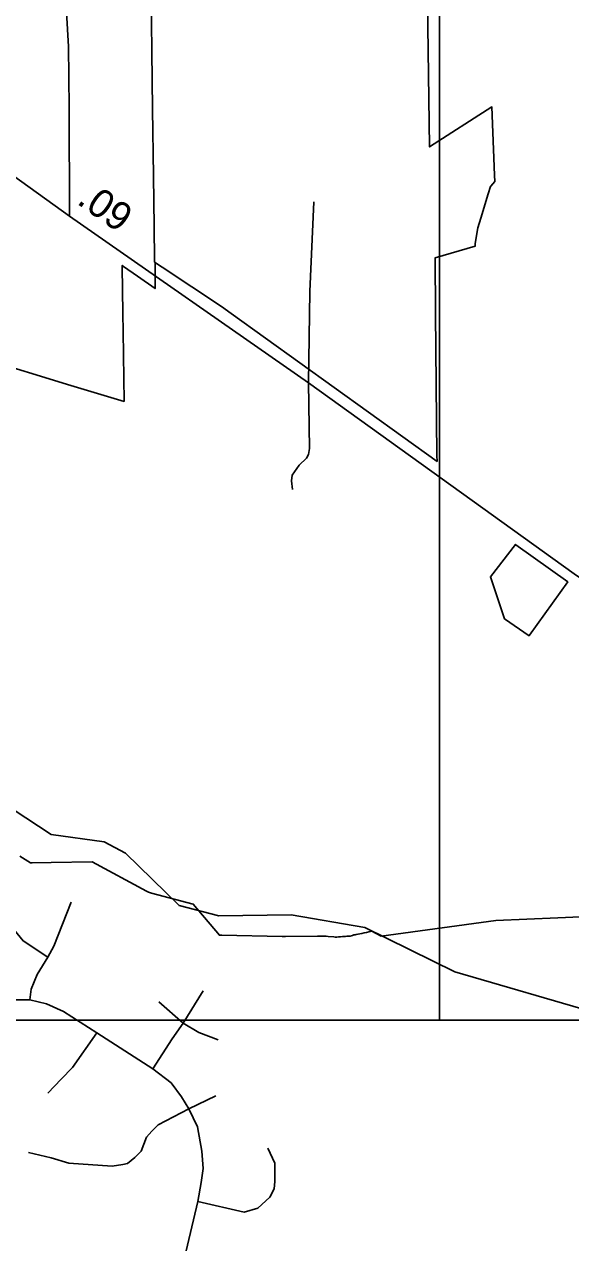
# Model space of a CAD drawing. Extents: x 2220236 to 2384410, y 720751 to 894131.
# Drawn here: x 2344280 to 2346680, y 815997 to 821350 of the extents above; entities that cross this region are included whole.
import ezdxf

# ---------------------------------------------------------------- set-up
doc = ezdxf.new("R2010")
doc.units = 0
doc.layers.add('Default', color=7, linetype='Continuous')

msp = doc.modelspace()

# ---------------------------------------------------------------- linework, layer by layer
at = {"layer": 'Default'}
for p, q in [((2344478.4, 820507.4), (2343633.8, 821113.6)), ((2344977.3, 816961.5), (2345064.7, 817103.7)), ((2344977.3, 816961.5), (2344871.2, 817055.7)), ((2344598, 816918.7), (2344843.8, 816761.2)), ((2345003, 816584.8), (2345121.2, 816641.3)), ((2345041.6, 816177.1), (2344925.1, 815683.9))]:
    msp.add_line(p, q, dxfattribs=at)
for points in [[(2329807.7, 835464.4), (2346103.7, 835464.4), (2346103.7, 816974.9), (2329807.7, 816974.9), (2329807.7, 835464.4)], [(2346103.7, 826026.5), (2370568.5, 826026.5), (2370568.5, 816974.7), (2346103.7, 816974.7), (2346103.7, 826026.5)], [(2344478.4, 820507.4), (2344476.5, 820982.7), (2344473, 821253.3), (2344445.1, 821731.6)], [(2346048.5, 821658.2), (2346060.2, 820811.6), (2346333.8, 820987.3), (2346345.2, 820687.1), (2346346.2, 820659.9), (2346329.2, 820639.2), (2346327.2, 820637.1), (2346317.5, 820604.6), (2346285, 820498), (2346272.2, 820455.7), (2346261, 820387.2), (2346260.2, 820383.2), (2346260.8, 820375.8), (2346084.8, 820324.8), (2346086.2, 820082.6), (2346086.2, 820079.4), (2346092.5, 819455.8), (2346092.8, 819429.9), (2345188.8, 820079.3), (2345146.5, 820109.7), (2344885, 820283.1), (2344864.2, 820297), (2344854, 820304.2), (2344852.2, 820305.6), (2344852, 820315.1), (2344850, 820460.7), (2344847, 820684.1), (2344843.2, 820976.9), (2344834.8, 821615.2)], [(2346048.5, 821658.2), (2346060.2, 820811.6), (2346333.8, 820987.3), (2346345.2, 820687.1), (2346346.2, 820659.9), (2346329.2, 820639.2), (2346327.2, 820637.1), (2346317.5, 820604.6), (2346285, 820498), (2346272.2, 820455.7), (2346261, 820387.2), (2346260.2, 820383.2), (2346260.8, 820375.8), (2346084.8, 820324.8), (2346086.2, 820082.6), (2346086.2, 820079.4), (2346092.5, 819455.8), (2346092.8, 819429.9), (2345188.8, 820079.3), (2345146.5, 820109.7), (2344885, 820283.1), (2344864.2, 820297), (2344854, 820304.2), (2344852.2, 820305.6), (2344852, 820315.1), (2344850, 820460.7), (2344847, 820684.1), (2344843.2, 820976.9), (2344834.8, 821615.2)], [(2344834.8, 821615.2), (2344843.2, 820976.9), (2344847, 820684.1), (2344850, 820460.7), (2344852, 820315.1), (2344852.2, 820305.6), (2344854, 820304.2), (2344854, 820279.7), (2344854, 820188.9), (2344777.2, 820242.9), (2344715.5, 820286.5), (2344709.5, 820290.6), (2344709.5, 820285.9), (2344712.5, 820079.3), (2344713.8, 820001.1), (2344718, 819692.9), (2344484, 819763.7), (2344091, 819882.6)], [(2344834.8, 821615.2), (2344843.2, 820976.9), (2344847, 820684.1), (2344850, 820460.7), (2344852, 820315.1), (2344852.2, 820305.6), (2344854, 820304.2), (2344854, 820279.7), (2344854, 820188.9), (2344777.2, 820242.9), (2344715.5, 820286.5), (2344709.5, 820290.6), (2344709.5, 820285.9), (2344712.5, 820079.3), (2344713.8, 820001.1), (2344718, 819692.9), (2344484, 819763.7), (2344091, 819882.6)], [(2345550.9, 820570.7), (2345534.6, 820176.2), (2345528.6, 819774.9)], [(2348124.6, 817788.7), (2347936.5, 817963.2), (2347678.1, 818197.7), (2347421.9, 818413.9), (2347207.1, 818583.8), (2346695.1, 818936.2), (2345528.6, 819774.9), (2344478.4, 820507.4)], [(2345458.5, 819305.9), (2345453.4, 819343.6), (2345456.8, 819369.2), (2345487.6, 819413.7), (2345520.1, 819444.5), (2345528.6, 819459.9), (2345532, 819485.6), (2345528.6, 819774.9)], [(2346805.5, 817002.9), (2346170.5, 817187), (2345776.4, 817380.9), (2345451.3, 817436.6), (2345134.3, 817433.5), (2344959.4, 817478.8), (2344723.4, 817708.8), (2344630.5, 817757.6), (2344397.4, 817790.6), (2344011.4, 818044), (2343719.4, 818048.5), (2343089.3, 818449.4), (2342894.3, 818730.3), (2342743.4, 818819.3), (2342400.3, 818966.1), (2342240.4, 819113.8)], [(2344259.8, 817695.5), (2344306, 817665.9), (2344314, 817666.1), (2344396.8, 817667.6), (2344577.2, 817670.8), (2344816.2, 817541.6), (2344825.8, 817536.3), (2344837.8, 817533.1), (2345022, 817484), (2345136.5, 817347.8), (2345147.5, 817347.5), (2345411.8, 817341.8), (2345427, 817342), (2345567, 817344), (2345581.5, 817343.1), (2345590.5, 817343.6), (2345597.2, 817343), (2345605.5, 817342.8), (2345614.8, 817341.9), (2345639.8, 817340.4), (2345645, 817339.8), (2345652.2, 817339.8), (2345660.5, 817340.6), (2345669.5, 817341.1), (2345677.5, 817341.4), (2345685.2, 817342), (2345691, 817342.4), (2345696.8, 817342.8), (2345704, 817343.3), (2345710.8, 817343.6), (2345721.2, 817346.6), (2345727.2, 817348.7), (2345732.8, 817350), (2345738, 817350.9), (2345745, 817351.8), (2345754, 817353.8), (2345761.8, 817355.6), (2345772.5, 817357.8), (2345783, 817359.8), (2345794, 817362.2), (2345800.5, 817363.9), (2345806.2, 817365.6), (2345847.8, 817343.4), (2346351.8, 817412.8), (2346624, 817424.3), (2346920.5, 817436.9)], [(2344259.8, 817695.5), (2344306, 817665.9), (2344314, 817666.1), (2344396.8, 817667.6), (2344577.2, 817670.8), (2344816.2, 817541.6), (2344825.8, 817536.3), (2344837.8, 817533.1), (2345022, 817484), (2345136.5, 817347.8), (2345147.5, 817347.5), (2345411.8, 817341.8), (2345427, 817342), (2345567, 817344), (2345581.5, 817343.1), (2345590.5, 817343.6), (2345597.2, 817343), (2345605.5, 817342.8), (2345614.8, 817341.9), (2345639.8, 817340.4), (2345645, 817339.8), (2345652.2, 817339.8), (2345660.5, 817340.6), (2345669.5, 817341.1), (2345677.5, 817341.4), (2345685.2, 817342), (2345691, 817342.4), (2345696.8, 817342.8), (2345704, 817343.3), (2345710.8, 817343.6), (2345721.2, 817346.6), (2345727.2, 817348.7), (2345732.8, 817350), (2345738, 817350.9), (2345745, 817351.8), (2345754, 817353.8), (2345761.8, 817355.6), (2345772.5, 817357.8), (2345783, 817359.8), (2345794, 817362.2), (2345800.5, 817363.9), (2345806.2, 817365.6), (2345847.8, 817343.4), (2346351.8, 817412.8), (2346624, 817424.3), (2346920.5, 817436.9)], [(2344382.2, 817251), (2344274.3, 817322.9), (2344234.9, 817370.9), (2344212.7, 817412), (2344193.8, 817477)], [(2344382.2, 817251), (2344409.6, 817298.9), (2344485, 817492.5)], [(2344303.4, 817064.3), (2344310.3, 817110.5), (2344336, 817175.6), (2344382.2, 817251)], [(2343873.6, 817062.6), (2344161.3, 817064.3), (2344303.4, 817064.3)], [(2344303.4, 817064.3), (2344377.1, 817045.5), (2344452.4, 817012.9), (2344598, 816918.7)], [(2329807.7, 816974.9), (2370566.3, 816974.8), (2370566.3, 785046.7), (2329807.6, 785046.7), (2329807.7, 816974.9)], [(2344843.8, 816761.2), (2344929.4, 816893), (2344977.3, 816961.5)], [(2344977.3, 816961.5), (2345045.9, 816920.4), (2345131.5, 816887.9)], [(2344598, 816918.7), (2344491.8, 816766.3), (2344442.1, 816714.9), (2344382.2, 816653.3)], [(2344843.8, 816761.2), (2344924.3, 816699.5), (2344970.5, 816637.8), (2345003, 816584.8)], [(2345003, 816584.8), (2344867.7, 816514.5), (2344840.3, 816487.1), (2344816.4, 816459.7), (2344792.4, 816398.1), (2344765, 816370.7), (2344732.4, 816345), (2344711.9, 816339.8), (2344665.6, 816333), (2344475.5, 816346.7), (2344396.8, 816369), (2344297.4, 816392.9)], [(2345003, 816584.8), (2345040.7, 816506), (2345059.6, 816398.1), (2345064.7, 816322.7), (2345056.1, 816261.1), (2345041.6, 816177.1)], [(2345041.6, 816177.1), (2345245.4, 816130.9), (2345305.3, 816148), (2345358.4, 816196), (2345377.2, 816233.7), (2345380.7, 816266.2), (2345380.7, 816346.7), (2345349.8, 816411.8)]]:
    msp.add_lwpolyline(points, dxfattribs=at)
msp.add_lwpolyline([(2346499.8, 818666.7), (2346497.5, 818663.5), (2346389.2, 818738.1), (2346387.5, 818742.7), (2346327.2, 818922.8), (2346437, 819064.6), (2346438.5, 819063.7), (2346667.5, 818899.9)], close=True, dxfattribs=at)
msp.add_lwpolyline([(2346499.8, 818666.7), (2346497.5, 818663.5), (2346389.2, 818738.1), (2346387.5, 818742.7), (2346327.2, 818922.8), (2346437, 819064.6), (2346438.5, 819063.7), (2346667.5, 818899.9)], close=True, dxfattribs=at)

# ---------------------------------------------------------------- texts
msp.add_text('.09', height=125, rotation=325.1037, dxfattribs=at).set_placement((2344505.6, 820564.6))

doc.saveas('drawing.dxf')
